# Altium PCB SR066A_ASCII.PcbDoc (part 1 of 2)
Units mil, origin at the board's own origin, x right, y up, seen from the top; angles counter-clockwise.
Board outline 2000 x 2000 mil, 4 copper layers (Top Layer, Signal Layer 1, Signal Layer 2, Bottom Layer), stack 60.434 mil thick; 64 components, 14 nets, 91 pads, 124 vias.
Unrouted connection lines stored in the file: 2.
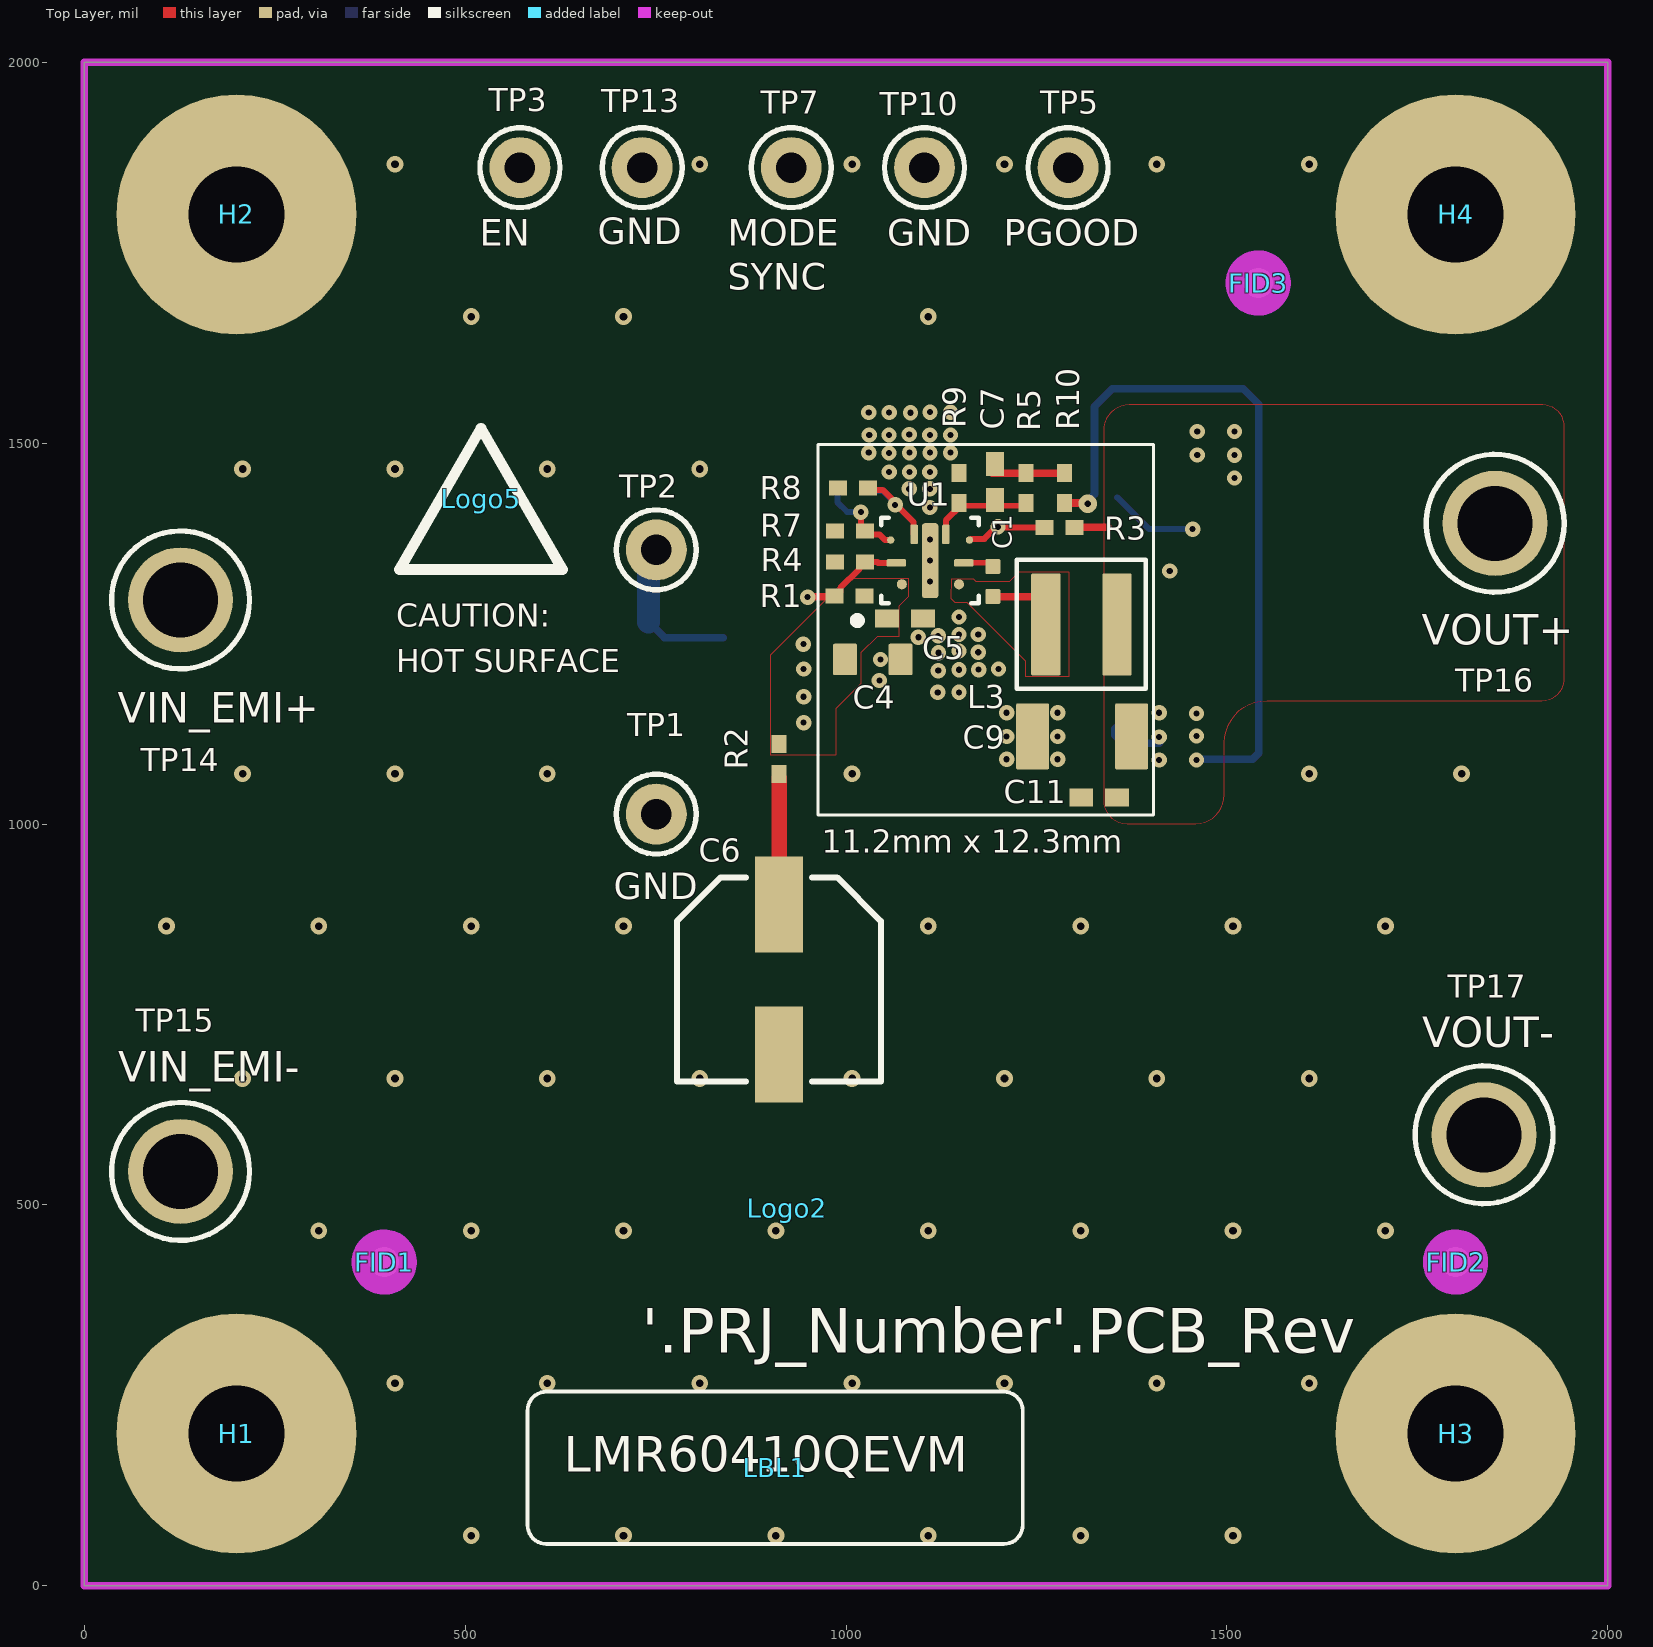
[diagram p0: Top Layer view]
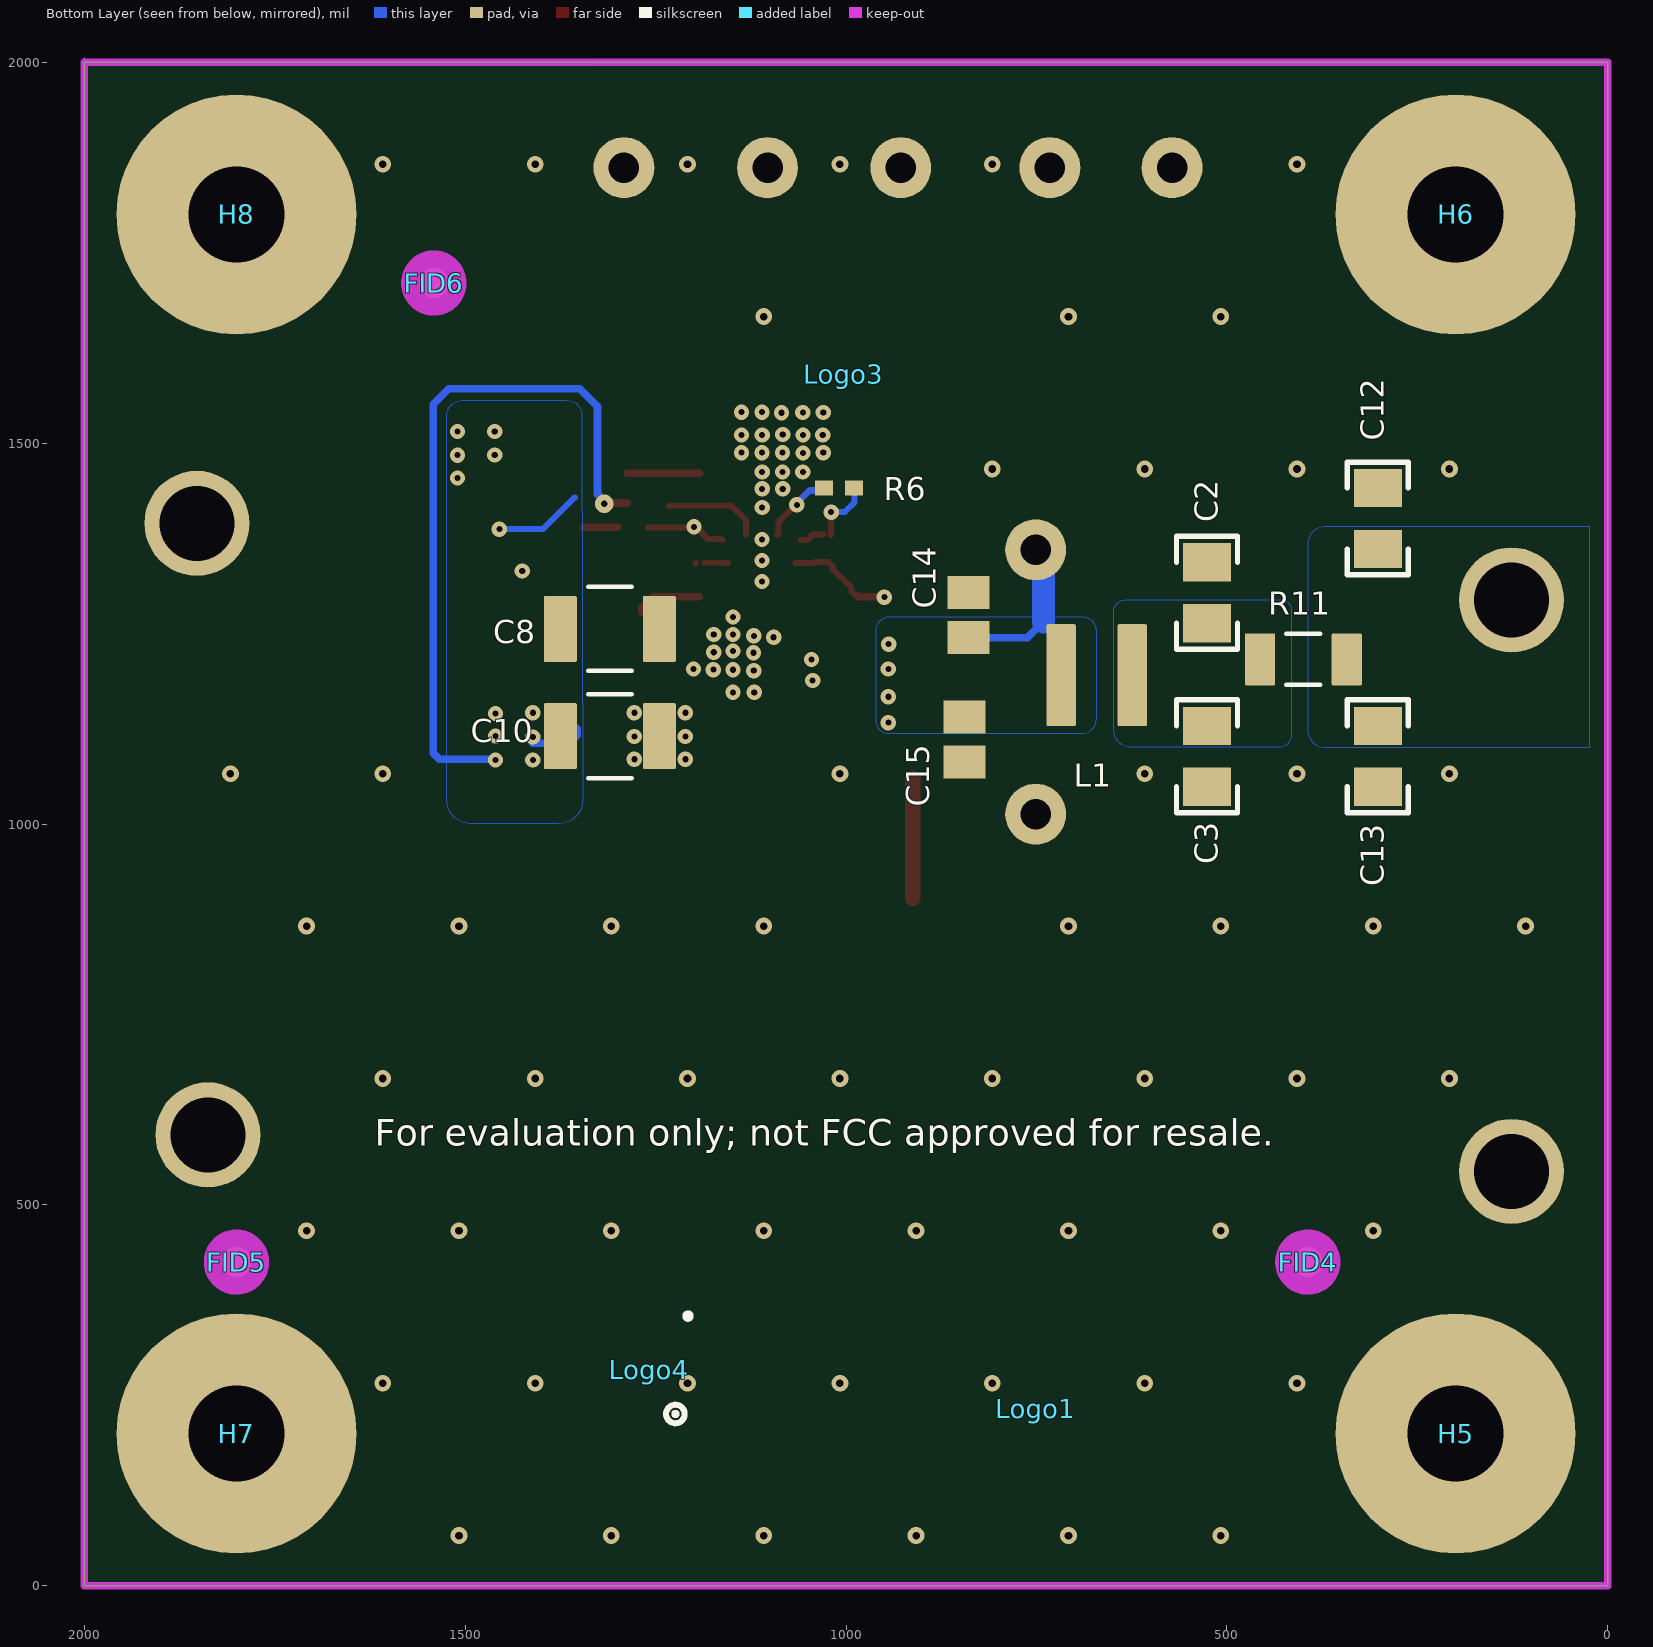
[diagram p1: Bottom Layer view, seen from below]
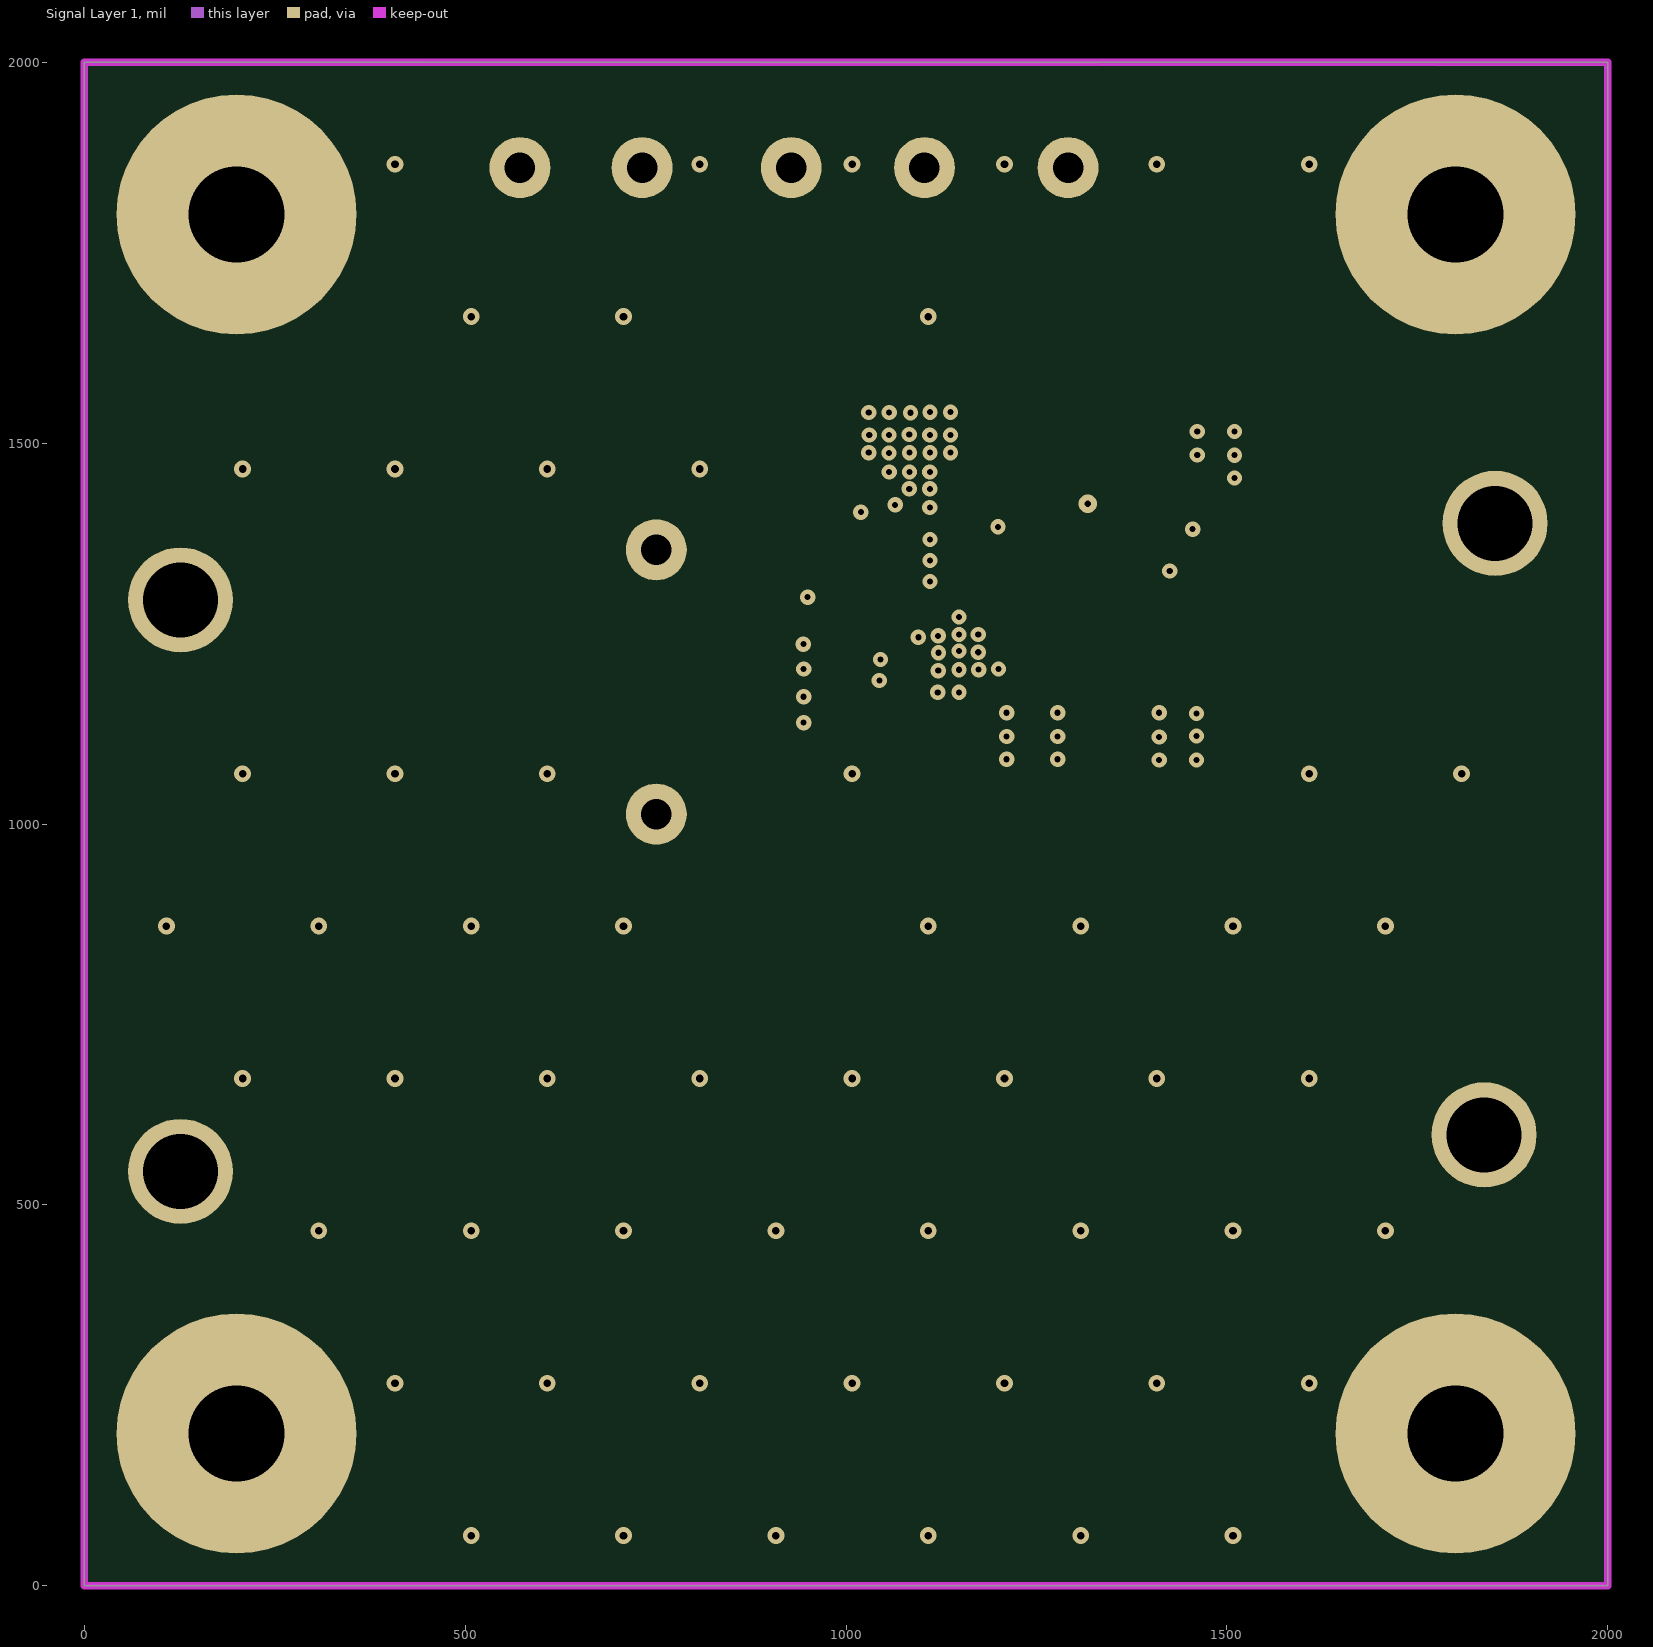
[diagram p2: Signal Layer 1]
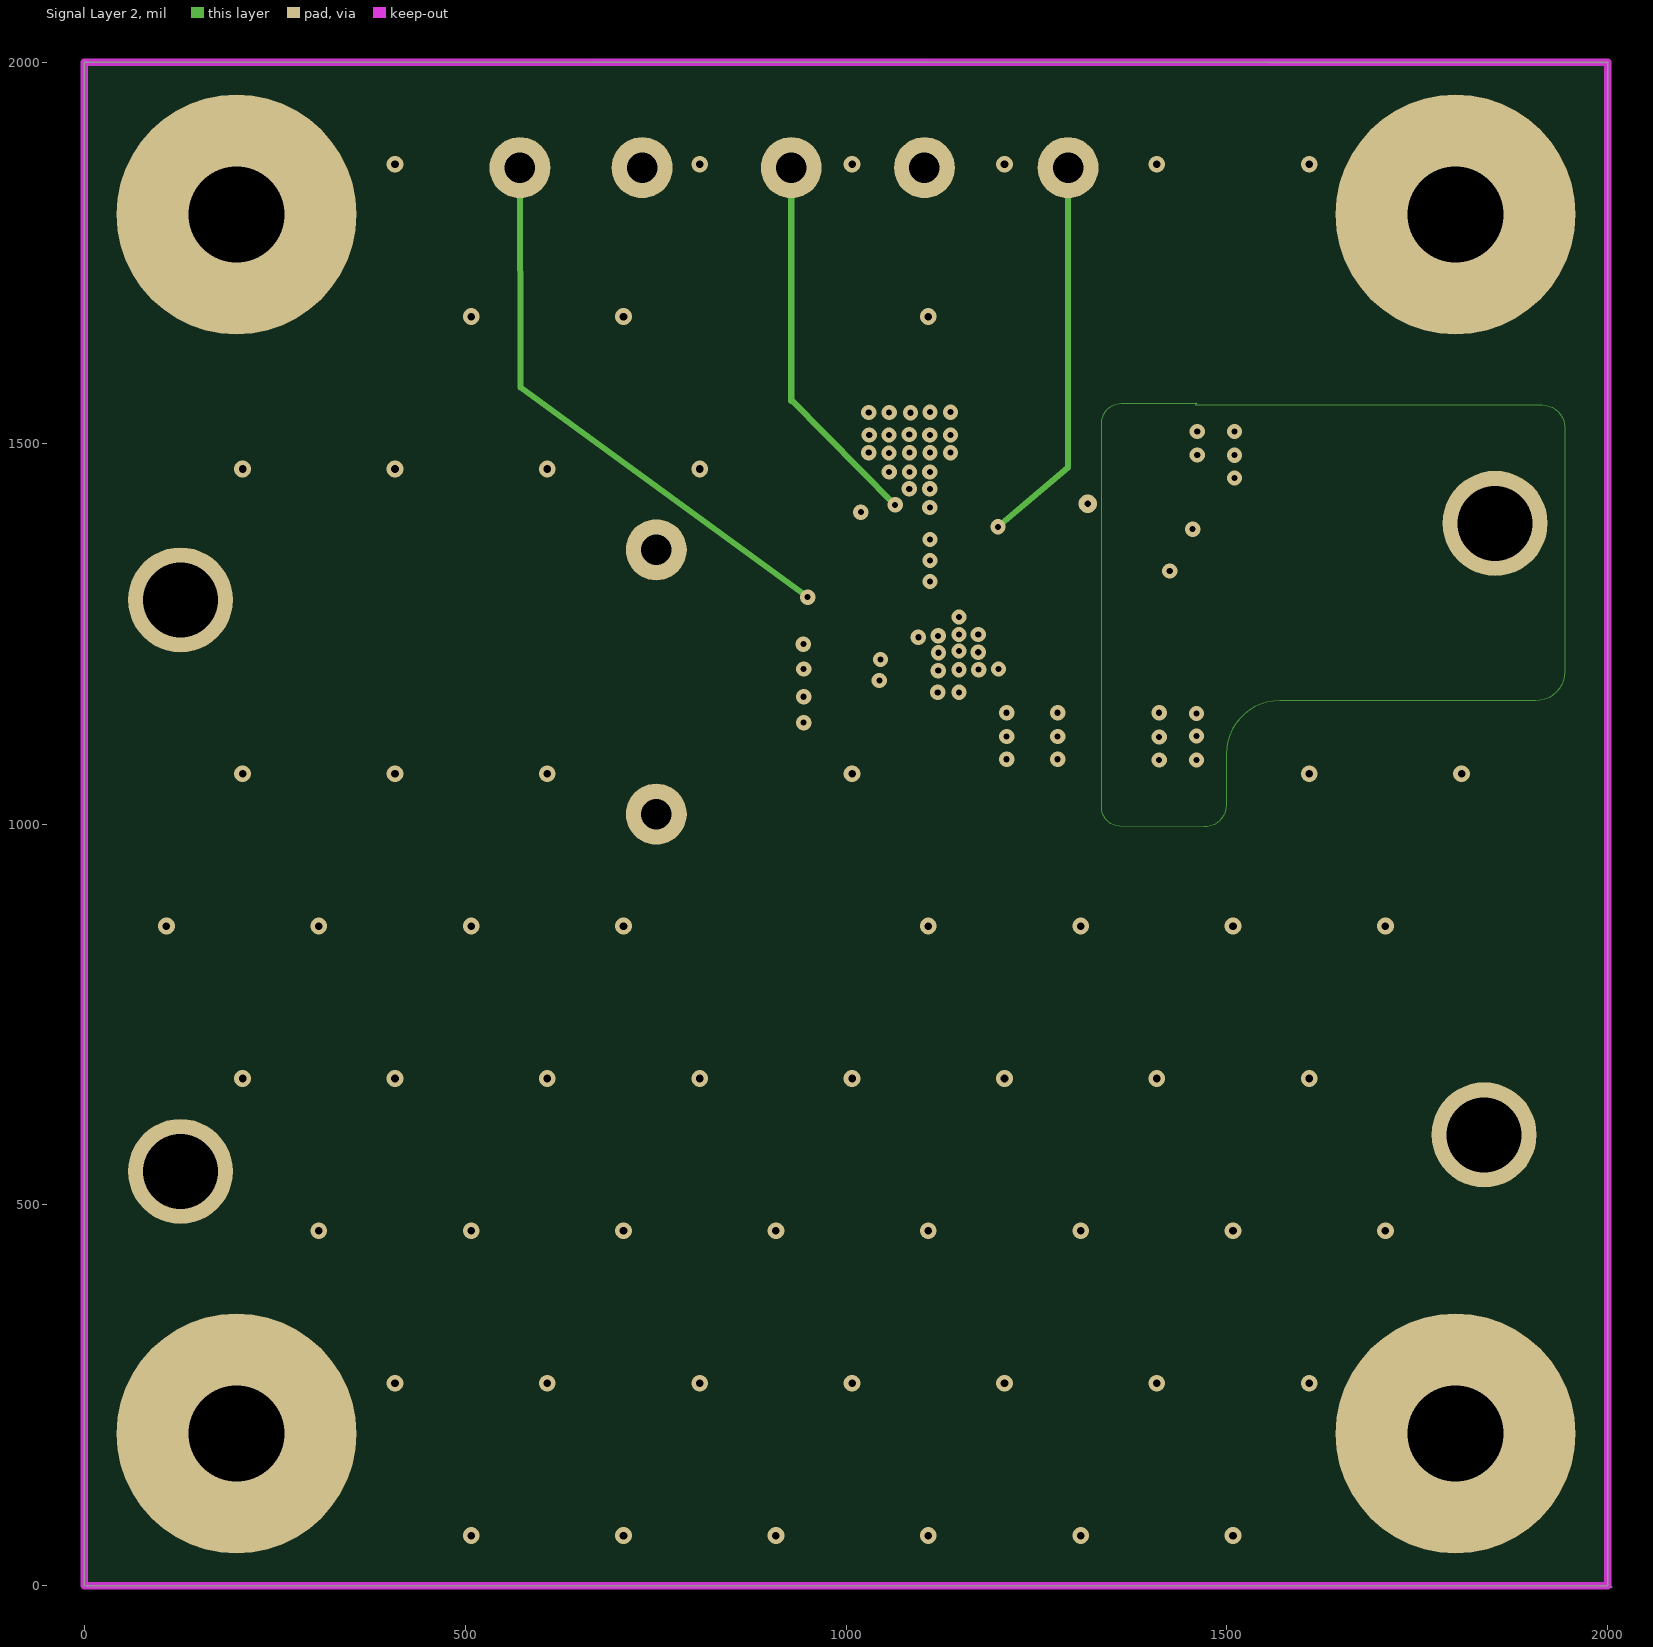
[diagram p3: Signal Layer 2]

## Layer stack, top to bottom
Top Solder: solder mask 0.4, Solder Resist, Dk 3.5
Top Layer: signal copper 2.8
Dielectric 1: core 10, FR-4 High Tg, Dk 4.2
Signal Layer 1: signal copper 1.417
Dielectric2: prepreg 32, FR-4 High Tg, Dk 4.2
Signal Layer 2: signal copper 1.417
Dielectric 3: core 10, FR-4 High Tg, Dk 4.2
Bottom Layer: signal copper 2.8
Bottom Solder: solder mask 0.4, Solder Resist, Dk 3.5

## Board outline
0,0 2000,0 2000,2000 0,2000

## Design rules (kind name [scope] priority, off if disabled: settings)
AcuteAngle [All] p0: scope1count=1 scope1_0_kind=Board scope1_0_value=Board scope2count=1 scope2_0_kind=Board scope2_0_value=Board commentlength=0 minimum=4.50000000000000E+0001
AcuteAngle [All] p1: minimum=4.50000000000000E+0001 checktracksonly=FALSE
AssemblyTestPointUsage [All] p0: scope1count=1 scope1_0_kind=Board scope1_0_value=Board scope2count=1 scope2_0_kind=Board scope2_0_value=Board commentlength=0
AssemblyTestPointUsage [All] p1: valid=2
AssemblyTestpoint [All] p0: scope1count=1 scope1_0_kind=Board scope1_0_value=Board scope2count=1 scope2_0_kind=Board scope2_0_value=Board commentlength=0
BoardOutlineClearance BoardOutlineClearance_MountingHoles [All] p0 off: scope1count=1 scope1_0_kind=Board scope1_0_value=Board scope2count=1 scope2_0_kind=Board scope2_0_value=Board commentlength=86 gap=39.37 // Protel DXP Scope 1 Expression Was: OnCopper and InComponentClass('Mounting Holes')
BoardOutlineClearance BoardOutlineClearance_Poly [All] p0 off: scope1count=1 scope1_0_kind=Board scope1_0_value=Board scope2count=1 scope2_0_kind=Board scope2_0_value=Board commentlength=58 gap=25 // Protel DXP Scope 1 Expression Was: OnCopper and IsPoly
BoardOutlineClearance [All] p0 off: scope1count=1 scope1_0_kind=Board scope1_0_value=Board scope2count=1 scope2_0_kind=Board scope2_0_value=Board commentlength=172 gap=50 // Protel DXP Scope 1 Expression Was: OnCopper and Not InComponentClass('Logo') and not InComponentClass('FiducialMark') and not InRegion(1000,500,4000,800) and not InPoly
BoardOutlineClearance BoardOutlineClearance_MountingHoles [OnCopper and InComponentClass('Mounting Holes')] p1: gap=39.37 ignorepadtopadclearanceinfootprint=FALSE
BoardOutlineClearance BoardOutlineClearance_Poly [OnCopper and IsPoly] p2: gap=25 ignorepadtopadclearanceinfootprint=FALSE
BoardOutlineClearance [OnCopper and Not InComponentClass('Logo') and not InComponentClass('FiducialMark') and not InRegion(1000,500,4000,800) and not InPoly] p3: gap=50 ignorepadtopadclearanceinfootprint=FALSE
Clearance Clearance_FB [All] p0: scope1count=2 scope1_0_kind=Net scope1_0_value=FB scope1_1_kind=Layer scope1_1_value=TOP scope2count=2 scope2_0_kind=Net scope2_0_value=GND scope2_1_kind=Layer scope2_1_value=TOP commentlength=0 gap=4.9
Clearance Clearance_ModeSync [All] p0: scope1count=2 scope1_0_kind=Net scope1_0_value=MODE/SYNC scope1_1_kind=Layer scope1_1_value=TOP scope2count=2 scope2_0_kind=Net scope2_0_value=GND scope2_1_kind=Layer scope2_1_value=TOP commentlength=0 gap=4.9
Clearance Clearance_Keepouts [All] p0 off: scope1count=1 scope1_0_kind=Board scope1_0_value=Board scope2count=1 scope2_0_kind=Board scope2_0_value=Board commentlength=99 gap=0 // Protel DXP Scope 2 Expression Was: ((IsTrack Or IsArc) And Not InPoly) And IsFree and IsKeepOut
Clearance Clearance_Poly [All] p0 off: scope1count=1 scope1_0_kind=Board scope1_0_value=Board scope2count=1 scope2_0_kind=Board scope2_0_value=Board commentlength=48 gap=8 // Protel DXP Scope 1 Expression Was: InPolygon
Clearance Clearance_FiducialMark [All] p0 off: scope1count=1 scope1_0_kind=Board scope1_0_value=Board scope2count=1 scope2_0_kind=Board scope2_0_value=Board commentlength=81 gap=0 // Protel DXP Scope 2 Expression Was: IsPad and InComponentClass('FiducialMark')
Clearance [All] p0: scope1count=1 scope1_0_kind=Board scope1_0_value=Board scope2count=1 scope2_0_kind=Board scope2_0_value=Board commentlength=0 gap=7.9
Clearance Clearance_Keepouts [((IsTrack Or IsArc) And Not InPoly) And IsFree and IsKeepOut vs ((IsTrack Or IsArc) And Not InPoly) And IsFree and IsKeepOut] p1: gap=0 ignorepadtopadclearanceinfootprint=FALSE
Clearance Clearance_Poly [InPolygon] p2: gap=8 ignorepadtopadclearanceinfootprint=TRUE
Clearance Clearance_FiducialMark [IsKeepOut and InComponentClass('FiducialMark') vs IsPad and InComponentClass('FiducialMark')] p3: gap=0 ignorepadtopadclearanceinfootprint=FALSE
Clearance Clearance_ModeSync [InNet('MODE/SYNC') And OnLayer('Top Layer') vs InNet('GND') And OnLayer('Top Layer')] p4: gap=4.9 ignorepadtopadclearanceinfootprint=FALSE
Clearance Clearance_FB [InNet('FB') And OnLayer('Top Layer') vs InNet('GND') And OnLayer('Top Layer')] p5: gap=4.9 ignorepadtopadclearanceinfootprint=FALSE
Clearance [All] p6: gap=7.9 ignorepadtopadclearanceinfootprint=TRUE except(5.9: SMDPad-Via)
ComponentClearance ComponentClearance_L2 [All] p0: scope1count=1 scope1_0_kind=Footprint scope1_0_value=FP-XGL4030-222MEC_SMT_IND_4MM0_4MM0-MFG scope2count=1 scope2_0_kind=Footprint scope2_0_value=FP-XGL6060-822MEC_SMT_IND_6MM51_6MM71-MFG commentlength=0 gap=0 collisioncheckmode=3
ComponentClearance ComponentClearance_MountingHoles_FiducialMarks [All] p0: scope1count=1 scope1_0_kind=ComponentClass scope1_0_value="Mounting Holes" scope2count=1 scope2_0_kind=ComponentClass scope2_0_value=FiducialMark commentlength=0 gap=50 collisioncheckmode=3
ComponentClearance ComponentClearance_Shunt [All] p0: scope1count=1 scope1_0_kind=ComponentClass scope1_0_value=Header scope2count=1 scope2_0_kind=ComponentClass scope2_0_value=Shunt commentlength=0 gap=0 collisioncheckmode=3
ComponentClearance ComponentClearance_Logo [All] p0: scope1count=1 scope1_0_kind=ComponentClass scope1_0_value=Logo scope2count=1 scope2_0_kind=Board scope2_0_value=Board commentlength=0 gap=50 collisioncheckmode=3
ComponentClearance ComponentClearance_ScrewToNut [All] p0 off: scope1count=1 scope1_0_kind=Board scope1_0_value=Board scope2count=1 scope2_0_kind=Board scope2_0_value=Board commentlength=71 gap=5 collisioncheckmode=3 // Protel DXP Scope 2 Expression Was: (HasFootprint('Keystone_1902C'))
ComponentClearance ComponentClearance_MountingHoles [All] p0: scope1count=1 scope1_0_kind=ComponentClass scope1_0_value="Mounting Holes" scope2count=1 scope2_0_kind=Board scope2_0_value=Board commentlength=0 gap=140 collisioncheckmode=3
ComponentClearance ComponentClearance_SmallPassives [All] p0 off: scope1count=1 scope1_0_kind=Board scope1_0_value=Board scope2count=1 scope2_0_kind=Board scope2_0_value=Board commentlength=508 gap=14.96 collisioncheckmode=3 // Protel DXP Scope 2 Expression Was: HasFootprint('0201*') or HasFootprint('0402*') or HasFootprint('0508') or HasFootprint('0603*') or HasFootprint('0612') or HasFootprint('0805*') or HasFootprint('0815*') or HasFootprint('0830*') or HasFootprint('1206*') or HasFootprint('1210*') or HasFootprint('1808*') or HasFootprint('1812*') or HasFootprint('1825*') or HasFootprint('2010*') or HasFootprint('2220*') or HasFootprint('2225*') or HasFootprint('2512*') or HasFootprint('2728*') or HasFootprint('3518*')
ComponentClearance ComponentClearance_THtoSMT [All] p0 off: scope1count=1 scope1_0_kind=Board scope1_0_value=Board scope2count=1 scope2_0_kind=Board scope2_0_value=Board commentlength=53 gap=40 collisioncheckmode=3 // Protel DXP Scope 2 Expression Was: IsSMTComponent
ComponentClearance ComponentClearance_THtoTH [All] p0 off: scope1count=1 scope1_0_kind=Board scope1_0_value=Board scope2count=1 scope2_0_kind=Board scope2_0_value=Board commentlength=54 gap=30 collisioncheckmode=3 // Protel DXP Scope 2 Expression Was: IsThruComponent
ComponentClearance [All] p0: scope1count=1 scope1_0_kind=Board scope1_0_value=Board scope2count=1 scope2_0_kind=Board scope2_0_value=Board commentlength=0 gap=14 collisioncheckmode=3
ComponentClearance ComponentClearance_MountingHoles_FiducialMarks [InComponentClass('Mounting Holes') vs InComponentClass('FiducialMark')] p1: gap=50 collisioncheckmode=3 verticalgap=10 showdistances=FALSE
ComponentClearance ComponentClearance_Shunt [InComponentClass('Header') vs InComponentClass('Shunt')] p2: gap=0 collisioncheckmode=3 verticalgap=0 showdistances=FALSE
ComponentClearance ComponentClearance_Logo [InComponentClass('Logo')] p3: gap=50 collisioncheckmode=3 verticalgap=10 showdistances=FALSE
ComponentClearance ComponentClearance_ScrewToNut [(HasFootprint('NY PMS 440 0025 PH')) vs (HasFootprint('Keystone_1902C'))] p4: gap=5 collisioncheckmode=3 verticalgap=10 showdistances=FALSE
ComponentClearance ComponentClearance_MountingHoles [InComponentClass('Mounting Holes')] p5: gap=140 collisioncheckmode=3 verticalgap=100000 showdistances=FALSE
ComponentClearance ComponentClearance_SmallPassives [HasFootprint('0201*') or HasFootprint('0402*') or HasFootprint('0508') or HasFootprint('0603*') or HasFootprint('0612') or HasFootprint('0805*') or HasFootprint('0815*') or HasFootprint('0830*') or HasFootprint('1206*') or HasFootprint('1210*') or HasFootprint('1808*') or HasFootprint('1812*') or HasFootprint('1825*') or HasFootprint('2010*') or HasFootprint('2220*') or HasFootprint('2225*') or HasFootprint('2512*') or HasFootprint('2728*') or HasFootprint('3518*') vs HasFootprint('0201*') or HasFootprint('0402*') or HasFootprint('0508') or HasFootprint('0603*') or HasFootprint('0612') or HasFootprint('0805*') or HasFootprint('0815*') or HasFootprint('0830*') or HasFootprint('1206*') or HasFootprint('1210*') or HasFootprint('1808*') or HasFootprint('1812*') or HasFootprint('1825*') or HasFootprint('2010*') or HasFootprint('2220*') or HasFootprint('2225*') or HasFootprint('2512*') or HasFootprint('2728*') or HasFootprint('3518*')] p6: gap=14.96 collisioncheckmode=3 verticalgap=10 showdistances=FALSE
ComponentClearance ComponentClearance_THtoSMT [IsThruComponent vs IsSMTComponent] p7: gap=40 collisioncheckmode=3 verticalgap=30 showdistances=FALSE
ComponentClearance ComponentClearance_THtoTH [IsThruComponent vs IsThruComponent] p8: gap=30 collisioncheckmode=3 verticalgap=30 showdistances=FALSE
ComponentClearance ComponentClearance_L2 [HasFootprint('FP-XGL4030-222MEC_SMT_IND_4MM0_4MM0-MFG') vs HasFootprint('FP-XGL6060-822MEC_SMT_IND_6MM51_6MM71-MFG')] p9: gap=0 collisioncheckmode=3 verticalgap=0 showdistances=FALSE
ComponentClearance [All] p10: gap=14 collisioncheckmode=3 verticalgap=10 showdistances=FALSE
DiffPairsRouting [All] p0: scope1count=1 scope1_0_kind=Board scope1_0_value=Board scope2count=1 scope2_0_kind=Board scope2_0_value=Board commentlength=0
DiffPairsRouting [All] p1: maxlimit=100 minlimit=10 mostfreqgap=10 toplayer_minwidth=15 toplayer_maxwidth=15 toplayer_prefwidth=15 midlayer1_minwidth=15 midlayer1_maxwidth=15 midlayer1_prefwidth=15 midlayer2_minwidth=15 midlayer2_maxwidth=15 midlayer2_prefwidth=15 bottomlayer_minwidth=15 bottomlayer_maxwidth=15 bottomlayer_prefwidth=15 maxuncoupledlength=1000
FabricationTestPointUsage TestPointUsage [All] p0: scope1count=1 scope1_0_kind=Board scope1_0_value=Board scope2count=1 scope2_0_kind=Board scope2_0_value=Board commentlength=0 valid=2 allowmultiple=FALSE
FabricationTestPointUsage TestPointUsage [All] p1: valid=2 allowmultiple=FALSE
FabricationTestpoint Testpoint [All] p0: scope1count=1 scope1_0_kind=Board scope1_0_value=Board scope2count=1 scope2_0_kind=Board scope2_0_value=Board commentlength=0 side=3 testpointundercomponent=TRUE minsize=40 maxsize=100 preferedsize=60 minholesize=0 maxholesize=40 preferedholesize=32 testpointgrid=1
FabricationTestpoint Testpoint [All] p1: side=3 testpointundercomponent=TRUE minsize=40 maxsize=100 preferedsize=60 minholesize=0 maxholesize=40 preferedholesize=32 testpointgrid=1 allowsidetop=TRUE allowsidebottom=TRUE usegrid=TRUE gridtolerance=0.01
FanoutControl Fanout_LCC [All] p0 off: scope1count=1 scope1_0_kind=Board scope1_0_value=Board scope2count=1 scope2_0_kind=Board scope2_0_value=Board commentlength=69 // Protel DXP Scope 1 Expression Was: IsLCC   Fanout_LCC (Default Rule)
FanoutControl Fanout_BGA [All] p0 off: scope1count=1 scope1_0_kind=Board scope1_0_value=Board scope2count=1 scope2_0_kind=Board scope2_0_value=Board commentlength=69 // Protel DXP Scope 1 Expression Was: IsBGA   Fanout_BGA (Default Rule)
FanoutControl Fanout_SOIC [All] p0 off: scope1count=1 scope1_0_kind=Board scope1_0_value=Board scope2count=1 scope2_0_kind=Board scope2_0_value=Board commentlength=71 // Protel DXP Scope 1 Expression Was: IsSOIC   Fanout_SOIC (Default Rule)
FanoutControl Fanout_Default [All] p0: scope1count=1 scope1_0_kind=Board scope1_0_value=Board scope2count=1 scope2_0_kind=Board scope2_0_value=Board commentlength=30 // Fanout_Default (Default Rule)
FanoutControl Fanout_Small [All] p0 off: scope1count=1 scope1_0_kind=Board scope1_0_value=Board scope2count=1 scope2_0_kind=Board scope2_0_value=Board commentlength=84 // Protel DXP Scope 1 Expression Was: (CompPinCount < 5)   Fanout_Small (Default Rule)
FanoutControl Fanout_LCC [IsLCC] p1: bgadir=Out bgaviamode=Centered fanoutstyle=Auto fanoutdirection=Alternating viagrid=1 // Fanout_LCC (Default Rule)
FanoutControl Fanout_BGA [IsBGA] p2: bgadir=Out bgaviamode=Centered fanoutstyle=Auto fanoutdirection=Alternating viagrid=1 // Fanout_BGA (Default Rule)
FanoutControl Fanout_Default [All] p4: bgadir=Out bgaviamode=Centered fanoutstyle=Auto fanoutdirection=Alternating viagrid=1 // Fanout_Default (Default Rule)
FanoutControl Fanout_Small [(CompPinCount < 5)] p5: bgadir=Out bgaviamode=Centered fanoutstyle=Auto fanoutdirection=OutThenIn viagrid=1 // Fanout_Small (Default Rule)
Height [All] p0: scope1count=1 scope1_0_kind=Board scope1_0_value=Board scope2count=1 scope2_0_kind=Board scope2_0_value=Board commentlength=0
HoleSize [All] p0: scope1count=1 scope1_0_kind=Board scope1_0_value=Board scope2count=1 scope2_0_kind=Board scope2_0_value=Board commentlength=0 absolutevalues=TRUE maxlimit=251 minlimit=7.87 maxpercent=80.000 minpercent=20.000
HoleSize [All] p1: absolutevalues=TRUE maxlimit=251 minlimit=7.87 maxpercent=80.000 minpercent=20.000
HoleToHoleClearance [All] p0: scope1count=1 scope1_0_kind=Board scope1_0_value=Board scope2count=1 scope2_0_kind=Board scope2_0_value=Board commentlength=0
LayerPairs [All] p0: scope1count=1 scope1_0_kind=Board scope1_0_value=Board scope2count=1 scope2_0_kind=Board scope2_0_value=Board commentlength=0 enforce=TRUE
MinimumAnnularRing MinimumAnnularRing_ThermalPadVias [All] p0 off: scope1count=1 scope1_0_kind=Board scope1_0_value=Board scope2count=1 scope2_0_kind=Board scope2_0_value=Board commentlength=63 minimumring=5.91 // Protel DXP Scope 1 Expression Was: IsVia and InAnyComponent
MinimumAnnularRing [All] p0: scope1count=1 scope1_0_kind=Board scope1_0_value=Board scope2count=1 scope2_0_kind=Board scope2_0_value=Board commentlength=0 minimumring=6
MinimumAnnularRing MinimumAnnularRing_ThermalPadVias [IsVia and InAnyComponent] p1: minimumring=5.91
MinimumAnnularRing [All] p2: minimumring=6
MinimumSolderMaskSliver MinimumSolderMaskSliver_Logo [All] p0: scope1count=1 scope1_0_kind=ComponentClass scope1_0_value=Logo scope2count=1 scope2_0_kind=ComponentClass scope2_0_value=Logo commentlength=0
MinimumSolderMaskSliver [All] p0: scope1count=1 scope1_0_kind=Board scope1_0_value=Board scope2count=1 scope2_0_kind=Board scope2_0_value=Board commentlength=0
MinimumSolderMaskSliver MinimumSolderMaskSliver_Logo [InComponentClass('Logo') vs InComponentClass('Logo')] p1: minsoldermaskwidth=0.7
MinimumSolderMaskSliver [All] p2: minsoldermaskwidth=3.94
NetAntennae [All] p0: scope1count=1 scope1_0_kind=Board scope1_0_value=Board scope2count=1 scope2_0_kind=Board scope2_0_value=Board commentlength=0
PasteMaskExpansion [All] p0: scope1count=1 scope1_0_kind=Board scope1_0_value=Board scope2count=1 scope2_0_kind=Board scope2_0_value=Board commentlength=0 expansion=0
PlaneClearance [All] p0: scope1count=1 scope1_0_kind=Board scope1_0_value=Board scope2count=1 scope2_0_kind=Board scope2_0_value=Board commentlength=0 clearance=9.84
PlaneClearance [All] p1: clearance=9.84
PlaneConnect [All] p0: scope1count=1 scope1_0_kind=Board scope1_0_value=Board scope2count=1 scope2_0_kind=Board scope2_0_value=Board commentlength=0 planeconnectstyle=Direct reliefexpansion=10 reliefentries=4 reliefconductorwidth=10 reliefairgap=10
PlaneConnect [All] p1: planeconnectstyle=Direct reliefexpansion=10 reliefentries=4 reliefconductorwidth=10 reliefairgap=10
PolygonConnect [All] p0: scope1count=1 scope1_0_kind=Board scope1_0_value=Board scope2count=1 scope2_0_kind=Board scope2_0_value=Board commentlength=0 connectstyle=Direct reliefconductorwidth=10 reliefentries=4 polygonreliefangle="90 Angle"
PolygonConnect [All] p1: connectstyle=Direct reliefconductorwidth=10 reliefentries=4 polygonreliefangle="90 Angle" airgapwidth=10
RoutingCorners [All] p0: scope1count=1 scope1_0_kind=Board scope1_0_value=Board scope2count=1 scope2_0_kind=Board scope2_0_value=Board commentlength=0 cornerstyle=45-Degree minsetback=100 maxsetback=100
RoutingLayers [All] p0: scope1count=1 scope1_0_kind=Board scope1_0_value=Board scope2count=1 scope2_0_kind=Board scope2_0_value=Board commentlength=0 top layer=Automatic mid layer 1=Automatic mid layer 2=Automatic bottom layer=Automatic
RoutingPriority [All] p0: scope1count=1 scope1_0_kind=Board scope1_0_value=Board scope2count=1 scope2_0_kind=Board scope2_0_value=Board commentlength=0
RoutingTopology [All] p0: scope1count=1 scope1_0_kind=Board scope1_0_value=Board scope2count=1 scope2_0_kind=Board scope2_0_value=Board commentlength=0 topology=Shortest
RoutingVias ThermalPadVias [All] p0 off: scope1count=1 scope1_0_kind=Board scope1_0_value=Board scope2count=1 scope2_0_kind=Board scope2_0_value=Board commentlength=63 holewidth=7.87 width=19.68 viastyle="Through Hole" minholewidth=7.87 minwidth=19.68 maxholewidth=12.99 maxwidth=23.62 // Protel DXP Scope 1 Expression Was: IsVia and InAnyComponent
RoutingVias [All] p0: scope1count=1 scope1_0_kind=Board scope1_0_value=Board scope2count=1 scope2_0_kind=Board scope2_0_value=Board commentlength=0 holewidth=8 width=20 viastyle="Through Hole" minholewidth=7.87 minwidth=19.68 maxholewidth=40 maxwidth=65
RoutingVias ThermalPadVias [IsVia and InAnyComponent] p1: holewidth=7.87 width=19.68 viastyle="Through Hole" minholewidth=7.87 minwidth=19.68 maxholewidth=12.99 maxwidth=23.62
RoutingVias [All] p2: holewidth=8 width=20 viastyle="Through Hole" minholewidth=7.87 minwidth=19.68 maxholewidth=40 maxwidth=65
ShortCircuit [All] p0: scope1count=1 scope1_0_kind=Board scope1_0_value=Board scope2count=1 scope2_0_kind=Board scope2_0_value=Board commentlength=0 allowed=FALSE
SilkToBoardRegionClearance [All] p0 off: scope1count=1 scope1_0_kind=Board scope1_0_value=Board scope2count=1 scope2_0_kind=Board scope2_0_value=Board commentlength=130 // Protel DXP Scope 1 Expression Was: Not ((IsComment or IsDesignator) And (Hide <> 'False')) and not InRegion(1000,500,4000,800)
SilkToBoardRegionClearance [Not ((IsComment or IsDesignator) And (Hide <> 'False')) and not InRegion(1000,500,4000,800)] p1:
SilkToSilkClearance SilkToSilkClearance_Pb-FreeLogo [All] p0 off: scope1count=1 scope1_0_kind=Board scope1_0_value=Board scope2count=1 scope2_0_kind=Board scope2_0_value=Board commentlength=120 // Protel DXP Scope 2 Expression Was: (HasFootprint('Pb-Free_Overlay_Medium') OR HasFootprint('Pb-Free_Overlay_Small'))
SilkToSilkClearance [All] p0: scope1count=1 scope1_0_kind=Board scope1_0_value=Board scope2count=1 scope2_0_kind=Board scope2_0_value=Board commentlength=0
SilkToSilkClearance SilkToSilkClearance_Pb-FreeLogo [(HasFootprint('Pb-Free_Overlay_Medium') OR HasFootprint('Pb-Free_Overlay_Small')) vs (HasFootprint('Pb-Free_Overlay_Medium') OR HasFootprint('Pb-Free_Overlay_Small'))] p1: silktosilkclearance=0
SilkToSilkClearance [All] p2: silktosilkclearance=3.94
SilkToSolderMaskClearance SilkToComponentPadClearance [All] p0 off: scope1count=1 scope1_0_kind=Board scope1_0_value=Board scope2count=1 scope2_0_kind=Board scope2_0_value=Board commentlength=87 // Protel DXP Scope 1 Expression Was: (IsPad or IsFill or IsRegion) and InAnycomponent
SilkToSolderMaskClearance "Silk to Solder Mask Opening" [All] p0: scope1count=1 scope1_0_kind=Board scope1_0_value=Board scope2count=1 scope2_0_kind=Board scope2_0_value=Board commentlength=0
SilkToSolderMaskClearance SilkToComponentPadClearance [(IsPad or IsFill or IsRegion) and InAnycomponent] p1: minsilkscreentomaskgap=5 clearancetoexposedcopper=TRUE
SilkToSolderMaskClearance "Silk to Solder Mask Opening" [All] p2: minsilkscreentomaskgap=3.94 clearancetoexposedcopper=FALSE
SolderMaskExpansion [All] p0: scope1count=1 scope1_0_kind=Board scope1_0_value=Board scope2count=1 scope2_0_kind=Board scope2_0_value=Board commentlength=0 expansion=1.97
SolderMaskExpansion [All] p1: expansion=1.97 istentingtop=FALSE
UnRoutedNet [All] p0: scope1count=1 scope1_0_kind=Board scope1_0_value=Board scope2count=1 scope2_0_kind=Board scope2_0_value=Board commentlength=0
UnRoutedNet [All] p1: checkbadconnections=TRUE
UnpouredPolygon [All] p0: scope1count=1 scope1_0_kind=Board scope1_0_value=Board scope2count=1 scope2_0_kind=Board scope2_0_value=Board commentlength=0
Width [All] p0: scope1count=1 scope1_0_kind=Board scope1_0_value=Board scope2count=1 scope2_0_kind=Board scope2_0_value=Board commentlength=0 maxlimit=100 minlimit=6 preferedwidth=10
Width [All] p1: maxlimit=100 minlimit=6 preferedwidth=10 checkconnectedcopper=TRUE
13 further rules are at their usual default settings.

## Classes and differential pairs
net class "EMI Class": NetC2_1 NetC12_1
component class SR066A_Schematic: C1 C2 C3 C4 C5 C6 C7 C8 C9 C10 C11 C12 C13 C14 C15 L1 L3 R1 R2 R3 R4 R5 R6 R7 R8 R9 R10 R11 TP1 TP2 TP3 TP5 TP7 TP10 TP13 TP14 TP15 TP16 TP17 U1
component class "Mounting Holes": H1 H2 H3 H4
component class Logo: Logo2
component class Label: LBL1
component class SR066A_Hardware: !PCB1 FID1 FID2 FID3 FID4 FID5 FID6 H1 H2 H3 H4 H5 H6 H7 H8 LBL1 Logo1 Logo2 Logo3 Logo4 Logo5 ZZ1 ZZ2 ZZ3 ZZ4
component class FiducialMark: FID1 FID2 FID3 FID4 FID5 FID6
component class AssemblyNote: ZZ1 ZZ2 ZZ3 ZZ4

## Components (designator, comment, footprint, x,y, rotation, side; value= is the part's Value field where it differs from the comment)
C1 "CS0402KRX7R8BB104" FP-CS0402KRX7R8BB104_0402-MFG 1192.85,1318.33 r270 top
C2 "CGA4J3X7R1H225K125AB" 0805_HV 526.11,1303.53 r90 bottom
C3 "CGA4J3X7R1H225K125AB" 0805_HV 526.11,1088.89 r270 bottom
C4 "C2012X7R1H475K125AC" FP-C2012X7R1H475K125AC_0805-MFG 1035.24,1215.94 r180 top
C5 "GCM155R71H104KE02D" 0402 1077.42,1269.75 r0 top
C6 "EEEFT1H470AP" Panasonic_D 911.95,796.17 r270 top
C7 "CGA2B2C0G1H220J050BA" 0402 1195.29,1448.62 r270 top
C8 "CGA6P1X7R1C226M250AC" FP-CGA6P1X7R1C226M250AC_1210-MFG 1309.97,1255.97 r0 bottom
C9 "CGA6P1X7R1C226M250AC" FP-CGA6P1X7R1C226M250AC_1210-MFG 1309.9,1114.95 r0 top
C10 "CGA6P1X7R1C226M250AC" FP-CGA6P1X7R1C226M250AC_1210-MFG 1309.9,1115.41 r0 bottom
C11 "GCM155R71H104KE02D" 0402 1332.39,1035 r180 top
C12 "CGA4J3X7R1H225K125AB" 0805_HV 302,1400.93 r90 bottom
C13 "CGA4J3X7R1H225K125AB" 0805_HV 302,1088.89 r270 bottom
C14 "CGA4J3X7R1H225K125AB" 0805L 839,1274 r90 bottom
C15 "CGA4J3X7R1H225K125AB" 0805L 844.62,1111.08 r270 bottom
FID1 "Fiducial" Fiducial10-20 393.92,425 r0 top
FID2 "Fiducial" Fiducial10-20 1800,425 r0 top
FID3 "Fiducial" Fiducial10-20 1541,1710 r0 top
FID4 "Fiducial" Fiducial10-20 393.92,425 r180 bottom
FID5 "Fiducial" Fiducial10-20 1800,425 r180 bottom
FID6 "Fiducial" Fiducial10-20 1541,1710 r180 bottom
H1 "NY PMS 440 0025 PH" "NY PMS 440 0025 PH" 200,200 r0 top
H2 "NY PMS 440 0025 PH" "NY PMS 440 0025 PH" 200,1800 r0 top
H3 "NY PMS 440 0025 PH" "NY PMS 440 0025 PH" 1800,200 r0 top
H4 "NY PMS 440 0025 PH" "NY PMS 440 0025 PH" 1800,1800 r0 top
H5 "1902C" Keystone_1902C 200,200 r180 bottom
H6 "1902C" Keystone_1902C 200,1800 r180 bottom
H7 "1902C" Keystone_1902C 1800,200 r180 bottom
H8 "1902C" Keystone_1902C 1800,1800 r180 bottom
L1 "XEL4020-222MEB" XEL4020 671,1195.27 r0 bottom
L3 "XGL4030-562MEC" FP-XGL4030-562MEC_SMT_IND_4MM0_4MM0-MFG 1309,1262 r0 top
LBL1 "THT-14-423-10" Label_650x200 907,155 r0 top
Logo1 "CE Mark" CE_Mark_5mm 751,232.35 r180 bottom
Logo2 "Texas Instruments" TI_Stacked_Overlay_Small 923,496 r0 top
Logo3 "FCC disclaimer" FCC_disclaimer 1003,1590 r180 bottom
Logo4 "WEEE logo" WEEE_Minimum 1258,284 r180 bottom
Logo5 "CAUTION HOT SURFACE" IEC_HotSurface_Small 521,1427 r0 top
R1 "CRCW040230K1FKED" 0402L 1004.46,1299.29 r0 top
R2 "RC0402JR-070RL" 0402L 912.28,1085.05 r90 top
R3 "CRCW0402100KJNED" 0402L 1280,1389.41 r180 top
R4 "AC0402FR-0710KL" 0402L 1005.55,1343.89 r0 top
R5 "RC0402JR-070RL" 0402L 1236,1440.92 r90 top
R6 "RC0402JR-070RL" 0402L 1009.26,1440.92 r0 bottom
R7 "CRCW040215K0FKED" 0402L 1005.25,1384.37 r0 top
R8 "RC0402JR-070RL" 0402L 1009.26,1441.12 r0 top
R9 "MCS0402MD1002BE100" 0402L 1148.42,1440.92 r270 top
R10 "RC0402JR-070RL" 0402L 1286.9,1440.92 r270 top
R11 "5108" FP-5108_1206-MFG 399.69,1215.97 r0 bottom
TP1 "5001" Keystone5001 751,1013 r90 top
TP2 "5000" Keystone5000 751,1359.84 r90 top
TP3 "5000" Keystone5000 572.05,1861.47 r180 top
TP5 "5002" Keystone5002 1291.44,1861.47 r0 top
TP7 "5004" Keystone5004 928.13,1861.47 r0 top
TP10 "5001" Keystone5001 1102.99,1861.47 r0 top
TP13 "5001" Keystone5001 732.44,1861.47 r0 top
TP14 "1502-2" Keystone1502-2 126.54,1294.12 r0 top
TP15 "1502-2" Keystone1502-2 126.54,544.05 r0 top
TP16 "1502-2" Keystone1502-2 1852,1394.69 r0 top
TP17 "1502-2" Keystone1502-2 1837.45,592.1 r0 top
U1 "LMR604103SRAKR" RAK0009A-MFG 1110.4,1345.61 r90 top
ZZ1 "This Assembly Note is for PCB labels only" AssemblyNoteLabel 93,2845 r0 top
ZZ2 "These assemblies are ESD sensitive, ESD precautions shall be observed." AssemblyNote 93,2732 r0 top
ZZ3 "These assemblies must be clean and free from flux and all contaminants. Use of no clean flux is not acceptable." AssemblyNote 94,2608 r0 top
ZZ4 "These assemblies must comply with workmanship standards IPC-A-610 Class 2, unless otherwise specified." AssemblyNote 89,2478 r0 top

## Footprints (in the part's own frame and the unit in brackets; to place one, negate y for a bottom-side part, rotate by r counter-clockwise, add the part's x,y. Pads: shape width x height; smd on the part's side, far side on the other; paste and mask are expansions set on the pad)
0402 [mm] "0402 from SM-752 data"
  rect 0.8x0.6 smd: 1(-0.6,0) 2(0.6,0)
0402L [mm] "0402 from SM-752 data"
  rect 0.6x0.5 smd: 1(-0.5,0) 2(0.5,0)
0805_HV [mil] "0805 with 30mil clearance between pads"
  rect 50x63 smd: 1(-40,0) 2(40,0)
  silkscreen extent -74,-40 74,40
0805L [mm] "0805 from SM-752 data"
  rect 1.1x1.4 smd: 1(-0.75,0) 2(0.75,0)
AssemblyNote [mil] "Assembly Note"
AssemblyNoteLabel [mil] "Assembly Note for PCB Labels"
CE_Mark_5mm [mil] "Minimum text height for CE Mark"
FCC_disclaimer [mil]
Fiducial10-20 [mm]
  round 1 smd mask+0: 1(0,0)
  Top Layer keep-out circle w1.178: c0,0 r0.5
FP-5108_1206-MFG [mm]
  rrect10% 1.01x1.73 smd paste+0 mask+0: 1(-1.445,0) 2(1.445,0)
  silkscreen extent -0.57,-0.85 0.57,0.85
FP-C2012X7R1H475K125AC_0805-MFG [mm]
  rrect13% 0.8x1.05 smd paste+0 mask+0: 1(-0.925,0) 2(0.925,0)
FP-CGA6P1X7R1C226M250AC_1210-MFG [mm]
  rrect9% 1.1x2.2 smd paste+0 mask+0: 1(-1.65,0) 2(1.65,0)
  silkscreen extent -0.72,-1.4 0.72,1.4
FP-CS0402KRX7R8BB104_0402-MFG [mm]
  rrect20% 0.5x0.5 smd paste+0 mask+0: 1(-0.5,0) 2(0.5,0)
FP-XGL4030-562MEC_SMT_IND_4MM0_4MM0-MFG [mm]
  rrect10% 0.98x3.4 smd paste+0 mask+0: 1(-1.185,0) 2(1.185,0)
  silkscreen extent -2.15,-2.15 2.15,2.15
IEC_HotSurface_Small [mil]
  silkscreen extent -107,-93 107,92
Keystone1502-2 [mm] "Double Turret"
  round 3.5 hole 2.5: 1(0,0)
  silkscreen extent -2.3,-2.3 2.3,2.3
Keystone5000 [mil] "For Keystone 500x miniature loop terminals"
  round 80 hole 40: 1(0,0)
  silkscreen extent -52,-52 52,52
Keystone5001 [mil] "For Keystone 500x miniature loop terminals"
  round 80 hole 40: 1(0,0)
  silkscreen extent -52,-52 52,52
Keystone5002 [mil] "For Keystone 500x miniature loop terminals"
  round 80 hole 40: 1(0,0)
  silkscreen extent -52,-52 52,52
Keystone5004 [mil] "For Keystone 500x miniature loop terminals"
  round 80 hole 40: 1(0,0)
  silkscreen extent -52,-52 52,52
Keystone_1902C [mil] "Hex Standoff, 4-40 threaded, nylon"
  round 1 on Mech4: 0(0,0)
Label_650x200 [mil] "Thermal Transfer Label"
  round 1 on Mech13: 0(0,0)
  silkscreen extent -325,-100 325,100
"NY PMS 440 0025 PH" [mm] "4-40 nylon screw and mounting hole"
  round 8 hole 3.2: 1(0,0)
Panasonic_D [mm] "SMD, 2-Leads, Dia 6.3mm"
  rect 3.2x1.6 smd: 1(-2.5,0) 2(2.5,0)
  silkscreen extent -3.4,-3.4 3.4,3.4
RAK0009A-MFG [mm]
  round 0.337 smd paste-1000 mask+0: 1(-0.787,0.943) 3(-0.787,-0.962)
  rrect36% 2.5x0.55 smd paste-1000 mask+0: 2(0,0)
  rrect40% 0.25x0.65 smd paste+0 mask+0: 4(-0.075,-1.125) 9(-0.075,1.125)
  round 0.247 smd paste+0 mask+0: 5(0.687,-1.312) 8(0.687,1.312)
  rrect40% 0.65x0.25 smd paste+0 mask+0: 6(0.875,-0.525) 7(0.875,0.525)
  silkscreen extent -2.12,-1.63 1.43,2.55
TI_Stacked_Overlay_Small [mil]
WEEE_Minimum [mil] "WEEElie bin"
  silkscreen extent 22,-71 54,74
XEL4020 [mm] "SMD, 2-Leads, Body 4x4mm, Pitch 2.37mm"
  rrect10% 0.98x3.4 smd: 1(-1.185,0) 2(1.185,0)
